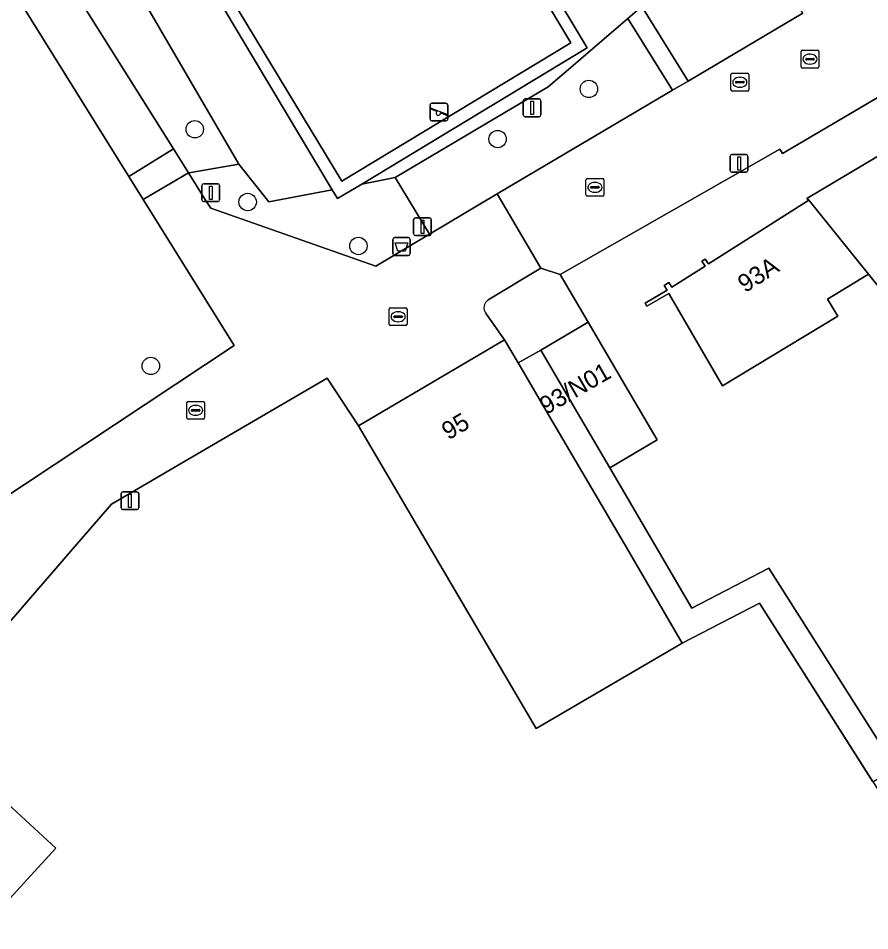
# Model space of a CAD drawing. Extents: x 161771 to 163125, y 382475 to 383179.
# Drawn here: x 162145.8 to 162193.8, y 382728.5 to 382779.9 of the extents above; entities that cross this region are included whole.
import ezdxf

# ---------------------------------------------------------------- set-up
doc = ezdxf.new("R2010")
doc.units = 0
for name, color, linetype in [('IMGEO_Afvalbak', 7, 'Continuous'), ('IMGEO_Boom', 7, 'Continuous'), ('IMGEO_Erf', 7, 'Continuous'), ('IMGEO_Groenvoorziening', 7, 'Continuous'), ('IMGEO_Hek', 7, 'Continuous'), ('IMGEO_Kolk', 7, 'Continuous'), ('IMGEO_Lichtmast', 7, 'Continuous'), ('IMGEO_Muur', 7, 'Continuous'), ('IMGEO_Pand', 7, 'Continuous'), ('IMGEO_Pand_nummerreeks', 7, 'Continuous'), ('IMGEO_Parkeervlak_open', 7, 'Continuous'), ('IMGEO_Rijbaan_lokaal_open', 7, 'Continuous'), ('IMGEO_Rioolput', 7, 'Continuous'), ('IMGEO_Speelvoorziening', 7, 'Continuous'), ('IMGEO_Terreindeel_gesloten', 7, 'Continuous'), ('IMGEO_Voetpad_open', 7, 'Continuous'), ('IMGEO_Woonerf_open', 7, 'Continuous')]:
    doc.layers.add(name, color=color, linetype=linetype)

msp = doc.modelspace()

# ---------------------------------------------------------------- linework, layer by layer
at = {"layer": 'IMGEO_Afvalbak'}
for p, q in [((162166.914, 382766.634), (162166.914, 382767.434)), ((162166.914, 382767.434), (162166.914, 382766.634)), ((162167.014, 382767.534), (162167.804, 382767.534)), ((162167.804, 382767.534), (162167.014, 382767.534)), ((162167.904, 382767.434), (162167.904, 382766.634)), ((162167.904, 382766.634), (162167.904, 382767.434)), ((162167.804, 382766.534), (162167.014, 382766.534)), ((162167.014, 382766.534), (162167.804, 382766.534))]:
    msp.add_line(p, q, dxfattribs=at)
msp.add_lwpolyline([(162167.057, 382767.248), (162167.761, 382767.248), (162167.612, 382766.778), (162167.206, 382766.778), (162167.057, 382767.248)], dxfattribs=at)
for centre, start, end in [((162167.014, 382767.434), 90, 180), ((162167.014, 382767.434), 90, 180), ((162167.804, 382767.434), 0, 90), ((162167.804, 382767.434), 360, 90), ((162167.014, 382766.634), 180, 270), ((162167.014, 382766.634), 180, 270), ((162167.804, 382766.634), 270, 0), ((162167.804, 382766.634), 270, 0)]:
    msp.add_arc(centre, 0.1, start, end, dxfattribs=at)
at = {"layer": 'IMGEO_Boom'}
for centre in [(162177.951, 382775.9), (162155.779, 382773.631), (162172.817, 382773.082), (162158.752, 382769.539), (162164.987, 382767.066), (162153.305, 382760.315)]:
    msp.add_circle(centre, 0.489, dxfattribs=at)
at = {"layer": 'IMGEO_Erf'}
for points in [[(162198.317, 382777.835), (162188.854, 382772.264), (162188.701, 382772.522), (162176.332, 382765.454), (162177.906, 382762.773), (162179.976, 382759.247), (162181.793, 382756.152), (162179.128, 382754.587), (162183.743, 382746.682), (162188.079, 382748.937), (162195.203, 382737.711)], [(162194.448, 382764.532), (162193.686, 382765.479), (162191.37, 382764.078), (162191.955, 382763.111), (162185.472, 382759.188), (162182.447, 382764.398), (162181.211, 382763.68), (162181.111, 382763.853), (162182.348, 382764.572), (162182.188, 382764.849), (162182.453, 382765.018), (162182.624, 382764.748), (162184.488, 382765.934), (162184.317, 382766.204), (162184.503, 382766.323), (162184.674, 382766.053), (162190.324, 382769.649), (162190.214, 382769.739), (162196.527, 382773.479)]]:
    msp.add_lwpolyline(points, dxfattribs=at)
at = {"layer": 'IMGEO_Groenvoorziening'}
for points in [[(162164.353, 382800.711), (162177.862, 382778.212), (162165.17, 382770.55), (162167.06, 382770.911), (162175.67, 382776.02), (162177.208, 382777.342), (162177.483, 382777.578), (162180.141, 382779.86), (162180.927, 382780.535)], [(162139.543, 382788.219), (162121.185, 382793.809), (162113.116, 382785.581), (162109.886, 382782.033), (162113.145, 382779.067), (162123.586, 382769.563), (162125.053, 382768.237), (162132.36, 382761.587), (162135.753, 382758.499), (162139.589, 382755.008), (162142.945, 382751.954), (162137.562, 382745.715), (162137.913, 382745.744), (162141.585, 382750), (162142.791, 382751.398), (162156.384, 382760.4), (162157.998, 382761.469), (162156.384, 382764.056), (162152.874, 382769.682), (162152.069, 382770.972), (162142.944, 382785.597)], [(162149.446, 382786.811), (162158.26, 382771.665), (162159.939, 382769.549), (162163.515, 382770.233), (162150.288, 382792.373)]]:
    msp.add_lwpolyline(points, dxfattribs=at)
for points in [[(162149.446, 382786.811), (162148.987, 382786.513), (162148.117, 382785.948), (162146.727, 382785.046), (162154.575, 382772.535), (162155.429, 382771.174), (162155.673, 382771.216), (162158.26, 382771.665)], [(162183.53, 382776.346), (162180.927, 382780.535), (162180.141, 382779.86), (162182.649, 382775.825)], [(162177.483, 382777.578), (162177.208, 382777.342), (162175.67, 382776.02), (162167.06, 382770.911), (162168.984, 382767.729), (162172.794, 382769.994), (162182.649, 382775.825), (162180.141, 382779.86)], [(162167.06, 382770.911), (162165.17, 382770.55), (162163.814, 382769.731), (162163.515, 382770.233), (162159.939, 382769.549), (162158.26, 382771.665), (162155.673, 382771.216), (162155.429, 382771.174), (162156.384, 382769.652), (162156.677, 382769.185), (162165.968, 382765.936), (162168.984, 382767.729)]]:
    msp.add_lwpolyline(points, close=True, dxfattribs=at)
at = {"layer": 'IMGEO_Hek'}
for points in [[(162158.26, 382771.665), (162155.673, 382771.216)], [(162167.06, 382770.911), (162168.984, 382767.729)]]:
    msp.add_lwpolyline(points, dxfattribs=at)
at = {"layer": 'IMGEO_Kolk'}
for p, q in [((162189.894, 382777.153), (162189.894, 382778.005)), ((162189.969, 382778.079), (162190.821, 382778.079)), ((162190.382, 382777.859), (162190.407, 382777.859)), ((162190.895, 382778.005), (162190.895, 382777.153)), ((162190.153, 382777.573), (162190.153, 382777.585)), ((162190.591, 382777.536), (162190.193, 382777.536)), ((162190.196, 382777.622), (162190.594, 382777.622)), ((162190.405, 382777.299), (162190.38, 382777.299)), ((162190.637, 382777.585), (162190.637, 382777.573)), ((162190.821, 382777.079), (162189.969, 382777.079)), ((162177.79, 382769.938), (162177.79, 382770.79)), ((162177.865, 382770.864), (162178.717, 382770.864)), ((162178.278, 382770.644), (162178.303, 382770.644)), ((162178.791, 382770.79), (162178.791, 382769.938)), ((162178.049, 382770.358), (162178.049, 382770.37)), ((162178.487, 382770.321), (162178.089, 382770.321)), ((162178.092, 382770.407), (162178.49, 382770.407)), ((162178.533, 382770.37), (162178.533, 382770.358)), ((162178.717, 382769.864), (162177.865, 382769.864)), ((162178.301, 382770.084), (162178.276, 382770.084)), ((162166.719, 382762.659), (162166.719, 382763.511)), ((162166.794, 382763.585), (162167.646, 382763.585)), ((162167.72, 382763.511), (162167.72, 382762.659)), ((162166.978, 382763.079), (162166.978, 382763.091)), ((162167.416, 382763.042), (162167.018, 382763.042)), ((162167.021, 382763.128), (162167.419, 382763.128)), ((162167.207, 382763.365), (162167.232, 382763.365)), ((162167.462, 382763.091), (162167.462, 382763.079)), ((162167.646, 382762.585), (162166.794, 382762.585)), ((162167.23, 382762.805), (162167.205, 382762.805)), ((162155.401, 382758.318), (162156.253, 382758.318)), ((162155.326, 382757.392), (162155.326, 382758.244)), ((162155.585, 382757.812), (162155.585, 382757.824)), ((162155.628, 382757.861), (162156.026, 382757.861)), ((162155.814, 382758.098), (162155.839, 382758.098)), ((162156.069, 382757.824), (162156.069, 382757.812)), ((162156.327, 382758.244), (162156.327, 382757.392)), ((162156.253, 382757.318), (162155.401, 382757.318)), ((162156.023, 382757.775), (162155.625, 382757.775)), ((162155.837, 382757.538), (162155.812, 382757.538))]:
    msp.add_line(p, q, dxfattribs=at)
for points in [[(162189.894, 382777.153), (162189.894, 382778.005)], [(162189.969, 382778.079), (162190.821, 382778.079)], [(162190.895, 382778.005), (162190.895, 382777.153)], [(162190.821, 382777.079), (162189.969, 382777.079)], [(162177.79, 382769.938), (162177.79, 382770.79)], [(162177.865, 382770.864), (162178.717, 382770.864)], [(162178.791, 382770.79), (162178.791, 382769.938)], [(162178.717, 382769.864), (162177.865, 382769.864)], [(162166.719, 382762.659), (162166.719, 382763.511)], [(162166.794, 382763.585), (162167.646, 382763.585)], [(162167.72, 382763.511), (162167.72, 382762.659)], [(162167.646, 382762.585), (162166.794, 382762.585)], [(162155.401, 382758.318), (162156.253, 382758.318)], [(162155.326, 382757.392), (162155.326, 382758.244)], [(162156.327, 382758.244), (162156.327, 382757.392)], [(162156.253, 382757.318), (162155.401, 382757.318)]]:
    msp.add_lwpolyline(points, dxfattribs=at)
for centre, radius, start, end in [((162189.971, 382778.003), 0.0765, 91.552, 178.448), ((162189.971, 382778.003), 0.0765, 91.552, 178.448), ((162190.819, 382778.003), 0.0765, 1.552, 88.448), ((162190.819, 382778.003), 0.0765, 1.552, 88.448), ((162190.193, 382777.582), 0.0403, 85.8775, 175.7526), ((162190.19, 382777.572), 0.0366, 178.938, 274.7102), ((162190.594, 382777.579), 0.043, 264.8664, 352.4533), ((162190.598, 382777.584), 0.0386, 1.7309, 96.639), ((162189.971, 382777.155), 0.0765, 181.552, 268.448), ((162189.971, 382777.155), 0.0765, 181.552, 268.448), ((162190.819, 382777.155), 0.0765, 271.552, 358.448), ((162190.819, 382777.155), 0.0765, 271.552, 358.448), ((162177.867, 382770.788), 0.0765, 91.552, 178.448), ((162177.867, 382770.788), 0.0765, 91.552, 178.448), ((162178.715, 382770.788), 0.0765, 1.552, 88.448), ((162178.715, 382770.788), 0.0765, 1.552, 88.448), ((162178.089, 382770.367), 0.0403, 85.8775, 175.7526), ((162178.086, 382770.357), 0.0366, 178.938, 274.7102), ((162178.49, 382770.364), 0.043, 264.8664, 352.4533), ((162178.494, 382770.369), 0.0386, 1.7309, 96.639), ((162177.867, 382769.94), 0.0765, 181.552, 268.448), ((162177.867, 382769.94), 0.0765, 181.552, 268.448), ((162178.715, 382769.94), 0.0765, 271.552, 358.448), ((162178.715, 382769.94), 0.0765, 271.552, 358.448), ((162166.796, 382763.509), 0.0765, 91.552, 178.448), ((162166.796, 382763.509), 0.0765, 91.552, 178.448), ((162167.644, 382763.509), 0.0765, 1.552, 88.448), ((162167.644, 382763.509), 0.0765, 1.552, 88.448), ((162167.018, 382763.088), 0.0403, 85.8775, 175.7526), ((162167.015, 382763.078), 0.0366, 178.938, 274.7102), ((162167.419, 382763.085), 0.043, 264.8664, 352.4533), ((162167.423, 382763.09), 0.0386, 1.7309, 96.639), ((162166.796, 382762.661), 0.0765, 181.552, 268.448), ((162166.796, 382762.661), 0.0765, 181.552, 268.448), ((162167.644, 382762.661), 0.0765, 271.552, 358.448), ((162167.644, 382762.661), 0.0765, 271.552, 358.448), ((162155.403, 382758.242), 0.0765, 91.552, 178.448), ((162155.403, 382758.242), 0.0765, 91.552, 178.448), ((162156.251, 382758.242), 0.0765, 1.552, 88.448), ((162156.251, 382758.242), 0.0765, 1.552, 88.448), ((162155.625, 382757.821), 0.0403, 85.8775, 175.7526), ((162155.622, 382757.811), 0.0366, 178.938, 274.7102), ((162156.026, 382757.818), 0.043, 264.8664, 352.4533), ((162156.03, 382757.823), 0.0386, 1.7309, 96.639), ((162155.403, 382757.394), 0.0765, 181.552, 268.448), ((162155.403, 382757.394), 0.0765, 181.552, 268.448), ((162156.251, 382757.394), 0.0765, 271.552, 358.448), ((162156.251, 382757.394), 0.0765, 271.552, 358.448)]:
    msp.add_arc(centre, radius, start, end, dxfattribs=at)
for centre, major_axis, ratio, start_param, end_param in [((162190.381, 382777.579), (-0.387, 0.002), 0.722429, 4.712389, 7.853982), ((162190.406, 382777.579), (-0.39, 0.002), 0.717154, 1.570796, 4.712389), ((162178.277, 382770.364), (-0.387, 0.002), 0.722429, 4.712389, 7.853982), ((162178.302, 382770.364), (-0.39, 0.002), 0.717154, 1.570796, 4.712389), ((162167.206, 382763.085), (-0.387, 0.002), 0.722429, 4.712389, 7.853982), ((162167.231, 382763.085), (-0.39, 0.002), 0.717154, 1.570796, 4.712389), ((162155.813, 382757.818), (-0.387, 0.002), 0.722429, 4.712389, 7.853982), ((162155.838, 382757.818), (-0.39, 0.002), 0.717154, 1.570796, 4.712389)]:
    msp.add_ellipse(centre, major_axis=major_axis, ratio=ratio, start_param=start_param, end_param=end_param, dxfattribs=at)
at = {"layer": 'IMGEO_Lichtmast'}
for p, q in [((162174.361, 382775.339), (162175.151, 382775.339)), ((162175.151, 382775.339), (162174.361, 382775.339)), ((162174.261, 382774.439), (162174.261, 382775.239)), ((162174.261, 382775.239), (162174.261, 382774.439)), ((162175.251, 382775.239), (162175.251, 382774.439)), ((162175.251, 382774.439), (162175.251, 382775.239)), ((162175.151, 382774.339), (162174.361, 382774.339)), ((162174.361, 382774.339), (162175.151, 382774.339)), ((162186.005, 382772.215), (162186.795, 382772.215)), ((162186.795, 382772.215), (162186.005, 382772.215)), ((162185.905, 382771.315), (162185.905, 382772.115)), ((162185.905, 382772.115), (162185.905, 382771.315)), ((162186.895, 382772.115), (162186.895, 382771.315)), ((162186.895, 382771.315), (162186.895, 382772.115)), ((162186.795, 382771.215), (162186.005, 382771.215)), ((162186.005, 382771.215), (162186.795, 382771.215)), ((162156.181, 382769.664), (162156.181, 382770.464)), ((162156.181, 382770.464), (162156.181, 382769.664)), ((162156.281, 382770.564), (162157.071, 382770.564)), ((162157.071, 382770.564), (162156.281, 382770.564)), ((162157.171, 382770.464), (162157.171, 382769.664)), ((162157.171, 382769.664), (162157.171, 382770.464)), ((162157.071, 382769.564), (162156.281, 382769.564)), ((162156.281, 382769.564), (162157.071, 382769.564)), ((162168.191, 382768.647), (162168.981, 382768.647)), ((162168.981, 382768.647), (162168.191, 382768.647)), ((162168.091, 382767.747), (162168.091, 382768.547)), ((162168.091, 382768.547), (162168.091, 382767.747)), ((162169.081, 382768.547), (162169.081, 382767.747)), ((162169.081, 382767.747), (162169.081, 382768.547)), ((162168.981, 382767.647), (162168.191, 382767.647)), ((162168.191, 382767.647), (162168.981, 382767.647)), ((162151.731, 382753.234), (162152.521, 382753.234)), ((162152.521, 382753.234), (162151.731, 382753.234)), ((162151.631, 382752.334), (162151.631, 382753.134)), ((162151.631, 382753.134), (162151.631, 382752.334)), ((162152.621, 382753.134), (162152.621, 382752.334)), ((162152.621, 382752.334), (162152.621, 382753.134)), ((162152.521, 382752.234), (162151.731, 382752.234)), ((162151.731, 382752.234), (162152.521, 382752.234))]:
    msp.add_line(p, q, dxfattribs=at)
for points in [[(162174.681, 382775.214), (162174.831, 382775.214), (162174.831, 382774.464), (162174.681, 382774.464), (162174.681, 382775.214)], [(162186.325, 382772.09), (162186.475, 382772.09), (162186.475, 382771.34), (162186.325, 382771.34), (162186.325, 382772.09)], [(162156.601, 382770.439), (162156.751, 382770.439), (162156.751, 382769.689), (162156.601, 382769.689), (162156.601, 382770.439)], [(162168.511, 382768.522), (162168.661, 382768.522), (162168.661, 382767.772), (162168.511, 382767.772), (162168.511, 382768.522)], [(162152.051, 382753.109), (162152.201, 382753.109), (162152.201, 382752.359), (162152.051, 382752.359), (162152.051, 382753.109)]]:
    msp.add_lwpolyline(points, dxfattribs=at)
for centre, start, end in [((162174.361, 382775.239), 90, 180), ((162174.361, 382775.239), 90, 180), ((162175.151, 382775.239), 0, 90), ((162175.151, 382775.239), 360, 90), ((162174.361, 382774.439), 180, 270), ((162174.361, 382774.439), 180, 270), ((162175.151, 382774.439), 270, 0), ((162175.151, 382774.439), 270, 0), ((162186.005, 382772.115), 90, 180), ((162186.005, 382772.115), 90, 180), ((162186.795, 382772.115), 0, 90), ((162186.795, 382772.115), 360, 90), ((162186.005, 382771.315), 180, 270), ((162186.005, 382771.315), 180, 270), ((162186.795, 382771.315), 270, 0), ((162186.795, 382771.315), 270, 0), ((162156.281, 382770.464), 90, 180), ((162156.281, 382770.464), 90, 180), ((162157.071, 382770.464), 0, 90), ((162157.071, 382770.464), 360, 90), ((162156.281, 382769.664), 180, 270), ((162156.281, 382769.664), 180, 270), ((162157.071, 382769.664), 270, 0), ((162157.071, 382769.664), 270, 0), ((162168.191, 382768.547), 90, 180), ((162168.191, 382768.547), 90, 180), ((162168.981, 382768.547), 0, 90), ((162168.981, 382768.547), 360, 90), ((162168.191, 382767.747), 180, 270), ((162168.191, 382767.747), 180, 270), ((162168.981, 382767.747), 270, 0), ((162168.981, 382767.747), 270, 0), ((162151.731, 382753.134), 90, 180), ((162151.731, 382753.134), 90, 180), ((162152.521, 382753.134), 0, 90), ((162152.521, 382753.134), 360, 90), ((162151.731, 382752.334), 180, 270), ((162151.731, 382752.334), 180, 270), ((162152.521, 382752.334), 270, 0), ((162152.521, 382752.334), 270, 0)]:
    msp.add_arc(centre, 0.1, start, end, dxfattribs=at)
at = {"layer": 'IMGEO_Muur'}
msp.add_lwpolyline([(162183.21, 382744.715), (162187.55, 382746.971), (162201.314, 382725.281)], dxfattribs=at)
at = {"layer": 'IMGEO_Pand'}
for points in [[(162200.56, 382766.385), (162196.527, 382773.479), (162190.214, 382769.739), (162190.324, 382769.649), (162190.419, 382769.539), (162193.686, 382765.479), (162194.448, 382764.532), (162195.372, 382763.383), (162197.938, 382764.858), (162201.076, 382759.395), (162203.659, 382760.932), (162202.197, 382763.505)], [(162193.686, 382765.479), (162190.419, 382769.539), (162190.324, 382769.649), (162184.674, 382766.053), (162184.503, 382766.323), (162184.317, 382766.204), (162184.488, 382765.934), (162182.624, 382764.748), (162182.453, 382765.018), (162182.188, 382764.849), (162182.348, 382764.572), (162181.111, 382763.853), (162181.211, 382763.68), (162182.447, 382764.398), (162185.472, 382759.188), (162191.955, 382763.111), (162191.37, 382764.078)], [(162177.906, 382762.773), (162175.241, 382761.208), (162177.311, 382757.682), (162179.128, 382754.587), (162181.793, 382756.152), (162179.976, 382759.247)], [(162173.21, 382761.784), (162164.986, 382756.953), (162167.518, 382752.642), (162169.068, 382750), (162174.988, 382739.908), (162183.21, 382744.715), (162180.116, 382750), (162175.742, 382757.473), (162173.974, 382760.484)]]:
    msp.add_lwpolyline(points, close=True, dxfattribs=at)
at = {"layer": 'IMGEO_Parkeervlak_open'}
msp.add_lwpolyline([(162187.356, 382784.521), (162183.863, 382782.355), (162180.927, 382780.535), (162183.53, 382776.346), (162190, 382780.174), (162189.158, 382781.558)], close=True, dxfattribs=at)
msp.add_lwpolyline([(162193.936, 382736.907), (162187.55, 382746.971), (162183.21, 382744.715), (162174.988, 382739.908), (162169.068, 382750), (162167.518, 382752.642), (162164.986, 382756.953), (162163.221, 382759.635), (162156.384, 382755.638), (162151.087, 382752.541), (162148.89, 382750), (162140.377, 382740.156), (162147.959, 382733.187), (162144.54, 382729.468)], dxfattribs=at)
at = {"layer": 'IMGEO_Rijbaan_lokaal_open'}
for points in [[(162146.727, 382785.046), (162146.458, 382785.475), (162146.143, 382785.978), (162145.275, 382787.36), (162142.824, 382785.83), (162142.944, 382785.597), (162152.069, 382770.972), (162154.575, 382772.535)], [(162152.069, 382770.972), (162152.874, 382769.682), (162155.429, 382771.174), (162154.575, 382772.535)]]:
    msp.add_lwpolyline(points, close=True, dxfattribs=at)
at = {"layer": 'IMGEO_Rioolput'}
for p, q in [((162185.947, 382775.854), (162185.947, 382776.706)), ((162186.022, 382776.78), (162186.874, 382776.78)), ((162186.206, 382776.274), (162186.206, 382776.286)), ((162186.249, 382776.323), (162186.647, 382776.323)), ((162186.435, 382776.56), (162186.46, 382776.56)), ((162186.69, 382776.286), (162186.69, 382776.274)), ((162186.948, 382776.706), (162186.948, 382775.854)), ((162186.874, 382775.78), (162186.022, 382775.78)), ((162186.644, 382776.237), (162186.246, 382776.237)), ((162186.458, 382776), (162186.433, 382776))]:
    msp.add_line(p, q, dxfattribs=at)
for points in [[(162185.947, 382775.854), (162185.947, 382776.706)], [(162186.022, 382776.78), (162186.874, 382776.78)], [(162186.948, 382776.706), (162186.948, 382775.854)], [(162186.874, 382775.78), (162186.022, 382775.78)]]:
    msp.add_lwpolyline(points, dxfattribs=at)
for centre, radius, start, end in [((162186.024, 382776.704), 0.0765, 91.552, 178.448), ((162186.024, 382776.704), 0.0765, 91.552, 178.448), ((162186.246, 382776.283), 0.0403, 85.8775, 175.7526), ((162186.243, 382776.273), 0.0366, 178.938, 274.7102), ((162186.647, 382776.28), 0.043, 264.8664, 352.4533), ((162186.651, 382776.285), 0.0386, 1.7309, 96.639), ((162186.872, 382776.704), 0.0765, 1.552, 88.448), ((162186.872, 382776.704), 0.0765, 1.552, 88.448), ((162186.024, 382775.856), 0.0765, 181.552, 268.448), ((162186.024, 382775.856), 0.0765, 181.552, 268.448), ((162186.872, 382775.856), 0.0765, 271.552, 358.448), ((162186.872, 382775.856), 0.0765, 271.552, 358.448)]:
    msp.add_arc(centre, radius, start, end, dxfattribs=at)
for centre, major_axis, ratio, start_param, end_param in [((162186.434, 382776.28), (-0.387, 0.002), 0.722429, 4.712389, 7.853982), ((162186.459, 382776.28), (-0.39, 0.002), 0.717154, 1.570796, 4.712389)]:
    msp.add_ellipse(centre, major_axis=major_axis, ratio=ratio, start_param=start_param, end_param=end_param, dxfattribs=at)
at = {"layer": 'IMGEO_Speelvoorziening'}
for p, q in [((162169.017, 382774.202), (162169.017, 382775.002)), ((162169.017, 382775.002), (162169.017, 382774.202)), ((162169.4, 382774.63), (162169.061, 382774.767)), ((162169.086, 382774.827), (162169.962, 382774.474)), ((162169.117, 382775.102), (162169.907, 382775.102)), ((162169.907, 382775.102), (162169.117, 382775.102)), ((162170.007, 382775.002), (162170.007, 382774.202)), ((162170.007, 382774.202), (162170.007, 382775.002)), ((162169.938, 382774.414), (162169.598, 382774.551)), ((162169.907, 382774.102), (162169.117, 382774.102)), ((162169.117, 382774.102), (162169.907, 382774.102))]:
    msp.add_line(p, q, dxfattribs=at)
for centre, radius, start, end in [((162169.117, 382775.002), 0.1, 90, 180), ((162169.117, 382775.002), 0.1, 90, 180), ((162169.074, 382774.797), 0.0327, 68.078, 248.078), ((162169.907, 382775.002), 0.1, 0, 90), ((162169.907, 382775.002), 0.1, 360, 90), ((162169.479, 382774.54), 0.12, 130.9928, 5.1632), ((162169.95, 382774.444), 0.0327, 248.078, 68.078), ((162169.117, 382774.202), 0.1, 180, 270), ((162169.117, 382774.202), 0.1, 180, 270), ((162169.907, 382774.202), 0.1, 270, 0), ((162169.907, 382774.202), 0.1, 270, 0)]:
    msp.add_arc(centre, radius, start, end, dxfattribs=at)
at = {"layer": 'IMGEO_Terreindeel_gesloten'}
for points in [[(162164.353, 382800.711), (162150.288, 382792.373), (162163.515, 382770.233), (162163.814, 382769.731), (162165.17, 382770.55), (162177.862, 382778.212)], [(162176.942, 382778.495), (162164.173, 382799.8), (162151.221, 382792.196), (162156.981, 382782.407), (162164.044, 382770.708)], [(162176.942, 382778.495), (162164.044, 382770.708), (162156.981, 382782.407), (162151.221, 382792.196), (162164.173, 382799.8)]]:
    msp.add_lwpolyline(points, close=True, dxfattribs=at)
at = {"layer": 'IMGEO_Voetpad_open'}
msp.add_lwpolyline([(162172.17, 382763.25), (162173.21, 382761.784), (162173.974, 382760.484), (162175.241, 382761.208), (162177.906, 382762.773), (162176.332, 382765.454), (162175.256, 382765.817), (162172.294, 382764.037)], dxfattribs=at)
msp.add_lwpolyline([(162177.311, 382757.682), (162175.241, 382761.208), (162173.974, 382760.484), (162175.742, 382757.473), (162180.116, 382750), (162183.21, 382744.715), (162187.55, 382746.971), (162193.936, 382736.907), (162195.203, 382737.711), (162188.079, 382748.937), (162183.743, 382746.682), (162179.128, 382754.587)], close=True, dxfattribs=at)
msp.add_arc((162172.581, 382763.588), 0.533, 122.6232, 219.469, dxfattribs=at)
at = {"layer": 'IMGEO_Woonerf_open'}
for points in [[(162190, 382780.174), (162183.53, 382776.346), (162182.649, 382775.825), (162172.794, 382769.994), (162175.256, 382765.817), (162176.332, 382765.454), (162188.701, 382772.522), (162188.854, 382772.264), (162198.317, 382777.835), (162200.759, 382776.963), (162201.192, 382776.242), (162204.442, 382778.142), (162205.237, 382776.753), (162209.001, 382778.957), (162208.186, 382780.333)], [(162172.294, 382764.037), (162175.256, 382765.817), (162172.794, 382769.994), (162168.984, 382767.729), (162165.968, 382765.936), (162156.677, 382769.185), (162156.384, 382769.652), (162155.429, 382771.174), (162152.874, 382769.682), (162156.384, 382764.056), (162157.998, 382761.469), (162156.384, 382760.4), (162142.791, 382751.398), (162141.585, 382750), (162137.913, 382745.744), (162132.852, 382740.143), (162139.628, 382733.955), (162144.54, 382729.468), (162147.959, 382733.187), (162140.377, 382740.156), (162148.89, 382750), (162151.087, 382752.541), (162156.384, 382755.638)], [(162156.384, 382755.638), (162163.221, 382759.635), (162164.986, 382756.953), (162173.21, 382761.784), (162172.17, 382763.25)]]:
    msp.add_lwpolyline(points, dxfattribs=at)
msp.add_arc((162172.581, 382763.588), 0.533, 122.6232, 219.469, dxfattribs=at)

# ---------------------------------------------------------------- texts
at = {"layer": 'IMGEO_Pand_nummerreeks'}
for s, rotation, p in [('93A', 32.4752, (162186.739, 382764.404)), ('93/N01', 29.811, (162175.546, 382757.552)), ('95', 30.4311, (162170.047, 382756.122))]:
    msp.add_text(s, height=1, rotation=rotation, dxfattribs=at).set_placement(p)

doc.saveas('drawing.dxf')
